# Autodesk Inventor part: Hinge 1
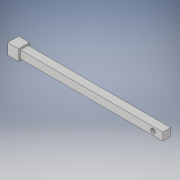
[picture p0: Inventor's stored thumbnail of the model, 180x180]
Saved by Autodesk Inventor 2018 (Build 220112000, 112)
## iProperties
Created: 2017-07
Part Number: Hinge 1
Material: Generic
Document SubType Name: Modeling
Designer: 17046589
Density: 1 g/cm^3
Appearance: Default
Author: 17046589
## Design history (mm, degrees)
sketch "Sketch1"
  geometry: L1 (0, 0)-(-10, 0); L2 (-10, 0)-(-10, -10); L3 (-10, -10)-(0, -10); L4 (0, -10)-(0, 0)
  constraints: 8 end point, 3 perpendicular, 1 horizontal
  dimensions: "d0" = 10 distance of L1.start L1.end; "d1" = 10 distance of L1.end L2.end
extrude "Extrusion1" new body sketch "Sketch1" distance "d2" = 10; taper "d3" = 0 deg
sketch "Sketch2"
  geometry: L1 (1.386, 8.512)-(8.528, 8.512); L2 (8.528, 8.512)-(8.528, 1.402); L3 (8.528, 1.402)-(1.386, 1.402); L4 (1.386, 1.402)-(1.386, 8.512); 1 further point
  constraints: 8 end point, 2 parallel, 1 horizontal, 1 perpendicular
extrude "Extrusion2" join sketch "Sketch2" distance "d4" = 130; taper "d5" = 0 deg
sketch "Sketch3"
  geometry: C1 r 2.204 at (121.075, 3.598); 1 further point
  constraints: 1 centre point
extrude "Extrusion3" cut sketch "Sketch3" distance "d6" = 130; taper "d7" = 0 deg
body "Solid1"
